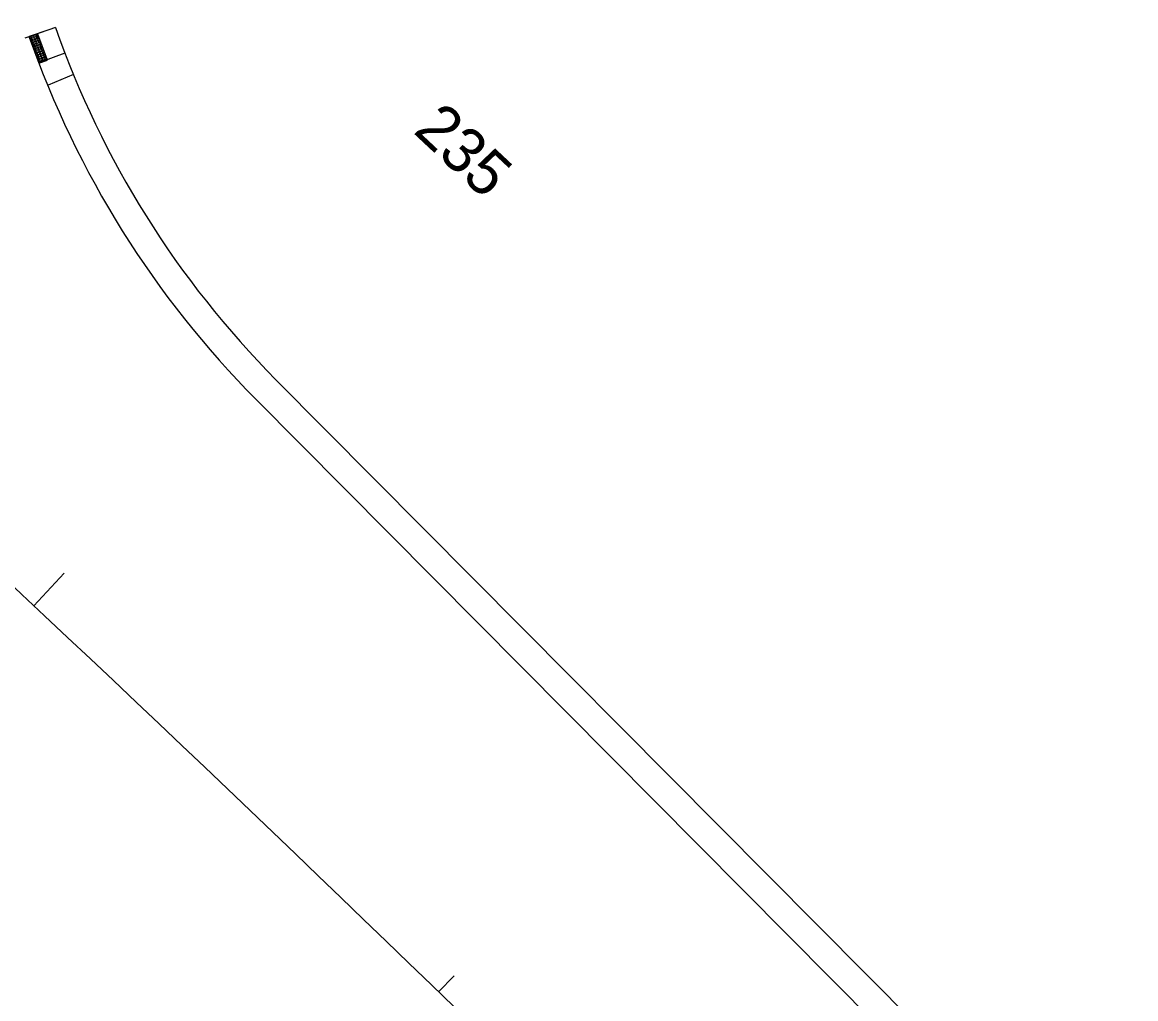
# Model space of a CAD drawing. Extents: x -5665 to 1997148, y 4 to 827579.
# Drawn here: x 1971970.2 to 1972169.2, y 802260.6 to 802435.1 of the extents above; entities that cross this region are included whole.
import ezdxf

# ---------------------------------------------------------------- set-up
doc = ezdxf.new("R2010")
doc.units = 0
for name, color, linetype in [('RD_HC_CL_Rel', 7, 'Continuous'), ('RD_HC_Data_Tic_Rel', 7, 'Continuous'), ('RD_HC_TX_Rel_Sta50', 7, 'Continuous'), ('RD_PD_SW', 7, 'Continuous')]:
    doc.layers.add(name, color=color, linetype=linetype)

msp = doc.modelspace()

# ---------------------------------------------------------------- linework, layer by layer
at = {"layer": 'RD_HC_CL_Rel'}
msp.add_arc((1968054.42, 798150.11), 5729.58, 44.809081, 48.405807, dxfattribs=at)
at = {"layer": 'RD_HC_Data_Tic_Rel'}
for p, q in [((1971972.28, 802330.82), (1971977.75, 802336.66)), ((1972044.65, 802261.81), (1972047.43, 802264.68))]:
    msp.add_line(p, q, dxfattribs=at)
at = {"layer": 'RD_PD_SW'}
for p, q in [((1971976.18, 802434.15), (1971970.71, 802432.24)), ((1971977.86, 802429.57), (1971973.19, 802427.79)), ((1971979.39, 802425.7), (1971974.86, 802423.83)), ((1972169.24, 802216.51), (1972015.58, 802371.19)), ((1972015.58, 802371.19), (1972169.24, 802216.51)), ((1972012.03, 802367.67), (1972165.53, 802213.14)), ((1972012.03, 802367.67), (1972165.53, 802213.14))]:
    msp.add_line(p, q, dxfattribs=at)
msp.add_lwpolyline([(1971976.18, 802434.15), (1971974.96, 802433.72), (1971971.46, 802432.5)], dxfattribs=at)
msp.add_lwpolyline([(1971974.72, 802428.29), (1971972.99, 802432.96), (1971971.49, 802432.4), (1971973.22, 802427.73)], close=True, dxfattribs=at)
for centre, radius in [((1971971.87, 802432.22), 0.146), ((1971971.87, 802432.22), 0.073), ((1971972.01, 802431.85), 0.146), ((1971972.01, 802431.85), 0.073), ((1971972.15, 802431.47), 0.146), ((1971972.15, 802431.47), 0.073), ((1971972.29, 802431.1), 0.146), ((1971972.34, 802432.4), 0.146), ((1971972.29, 802431.1), 0.073), ((1971972.34, 802432.4), 0.073), ((1971972.48, 802432.02), 0.146), ((1971972.48, 802432.02), 0.073), ((1971972.61, 802431.65), 0.146), ((1971972.61, 802431.65), 0.073), ((1971972.75, 802431.27), 0.146), ((1971972.81, 802432.57), 0.146), ((1971972.75, 802431.27), 0.073), ((1971972.81, 802432.57), 0.073), ((1971972.95, 802432.2), 0.146), ((1971972.95, 802432.2), 0.073), ((1971973.09, 802431.82), 0.146), ((1971973.09, 802431.82), 0.073), ((1971973.23, 802431.45), 0.146), ((1971973.23, 802431.45), 0.073), ((1971973.37, 802431.07), 0.146), ((1971973.37, 802431.07), 0.073), ((1971972.42, 802430.72), 0.146), ((1971972.42, 802430.72), 0.073), ((1971972.56, 802430.35), 0.146), ((1971972.56, 802430.35), 0.073), ((1971972.7, 802429.97), 0.146), ((1971972.7, 802429.97), 0.073), ((1971972.84, 802429.6), 0.146), ((1971972.89, 802430.9), 0.146), ((1971972.84, 802429.6), 0.073), ((1971972.89, 802430.9), 0.073), ((1971972.98, 802429.22), 0.146), ((1971973.03, 802430.52), 0.146), ((1971972.98, 802429.22), 0.073), ((1971973.03, 802430.52), 0.073), ((1971973.17, 802430.15), 0.146), ((1971973.17, 802430.15), 0.073), ((1971973.31, 802429.77), 0.146), ((1971973.31, 802429.77), 0.073), ((1971973.45, 802429.39), 0.146), ((1971973.51, 802430.7), 0.146), ((1971973.45, 802429.39), 0.073), ((1971973.51, 802430.7), 0.073), ((1971973.59, 802429.02), 0.146), ((1971973.65, 802430.32), 0.146), ((1971973.59, 802429.02), 0.073), ((1971973.65, 802430.32), 0.073), ((1971973.79, 802429.95), 0.146), ((1971973.79, 802429.95), 0.073), ((1971973.93, 802429.57), 0.146), ((1971973.93, 802429.57), 0.073), ((1971974.06, 802429.2), 0.146), ((1971974.06, 802429.2), 0.073), ((1971973.12, 802428.85), 0.146), ((1971973.12, 802428.85), 0.073), ((1971973.26, 802428.47), 0.146), ((1971973.26, 802428.47), 0.073), ((1971973.4, 802428.1), 0.146), ((1971973.4, 802428.1), 0.073), ((1971973.73, 802428.64), 0.146), ((1971973.73, 802428.64), 0.073), ((1971973.86, 802428.27), 0.146), ((1971973.86, 802428.27), 0.073), ((1971974.2, 802428.82), 0.146), ((1971974.2, 802428.82), 0.073), ((1971974.34, 802428.45), 0.146), ((1971974.34, 802428.45), 0.073)]:
    msp.add_circle(centre, radius, dxfattribs=at)
for radius in [168, 168, 173, 173]:
    msp.add_arc((1972134.77, 802489.59), radius, 199.268, 224.8091, dxfattribs=at)

# ---------------------------------------------------------------- texts
at = {"layer": 'RD_HC_TX_Rel_Sta50'}
msp.add_text('235', height=8, rotation=316.859, dxfattribs=at).set_placement((1972039.93, 802415.44))

doc.saveas('drawing.dxf')
